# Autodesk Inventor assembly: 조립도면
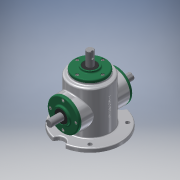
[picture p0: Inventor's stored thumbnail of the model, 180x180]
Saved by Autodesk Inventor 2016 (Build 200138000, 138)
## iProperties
Created: 2018-04
Part Number: 조립도면
Material: 일반
Document SubType Name: Assembly
Designer: 605-07
Author: 605-07
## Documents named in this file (16)
- C:\Users\605-07\Desktop\480407v1011 (2)\조립도면.iam
- C:\Users\605-07\Desktop\480407v1011 (2)\본체.ipt
- C:\Users\605-07\Desktop\480407v1011 (2)\메인 베벨기어.ipt
- C:\Users\605-07\Desktop\480407v1011 (2)\메인 축.ipt
- 메인 축.ipt
- C:\Users\605-07\Desktop\480407v1011 (2)\베어링 6203.ipt
- C:\Users\605-07\Desktop\480407v1011 (2)\볼트 M4.ipt
- 볼트 M4.ipt
- C:\Users\605-07\Desktop\480407v1011 (2)\서브 베벨기어.ipt
- C:\Users\605-07\Desktop\480407v1011 (2)\서브 축.ipt
- 서브 축.ipt
- C:\Users\605-07\Desktop\480407v1011 (2)\오일 실.ipt
- 오일 실.ipt
- C:\Users\605-07\Desktop\480407v1011 (2)\커버.ipt
- C:\Users\605-07\Desktop\480407v1011 (2)\키 4x4.ipt
- C:\Users\605-07\Desktop\480407v1011 (2)\키 5x5.ipt
